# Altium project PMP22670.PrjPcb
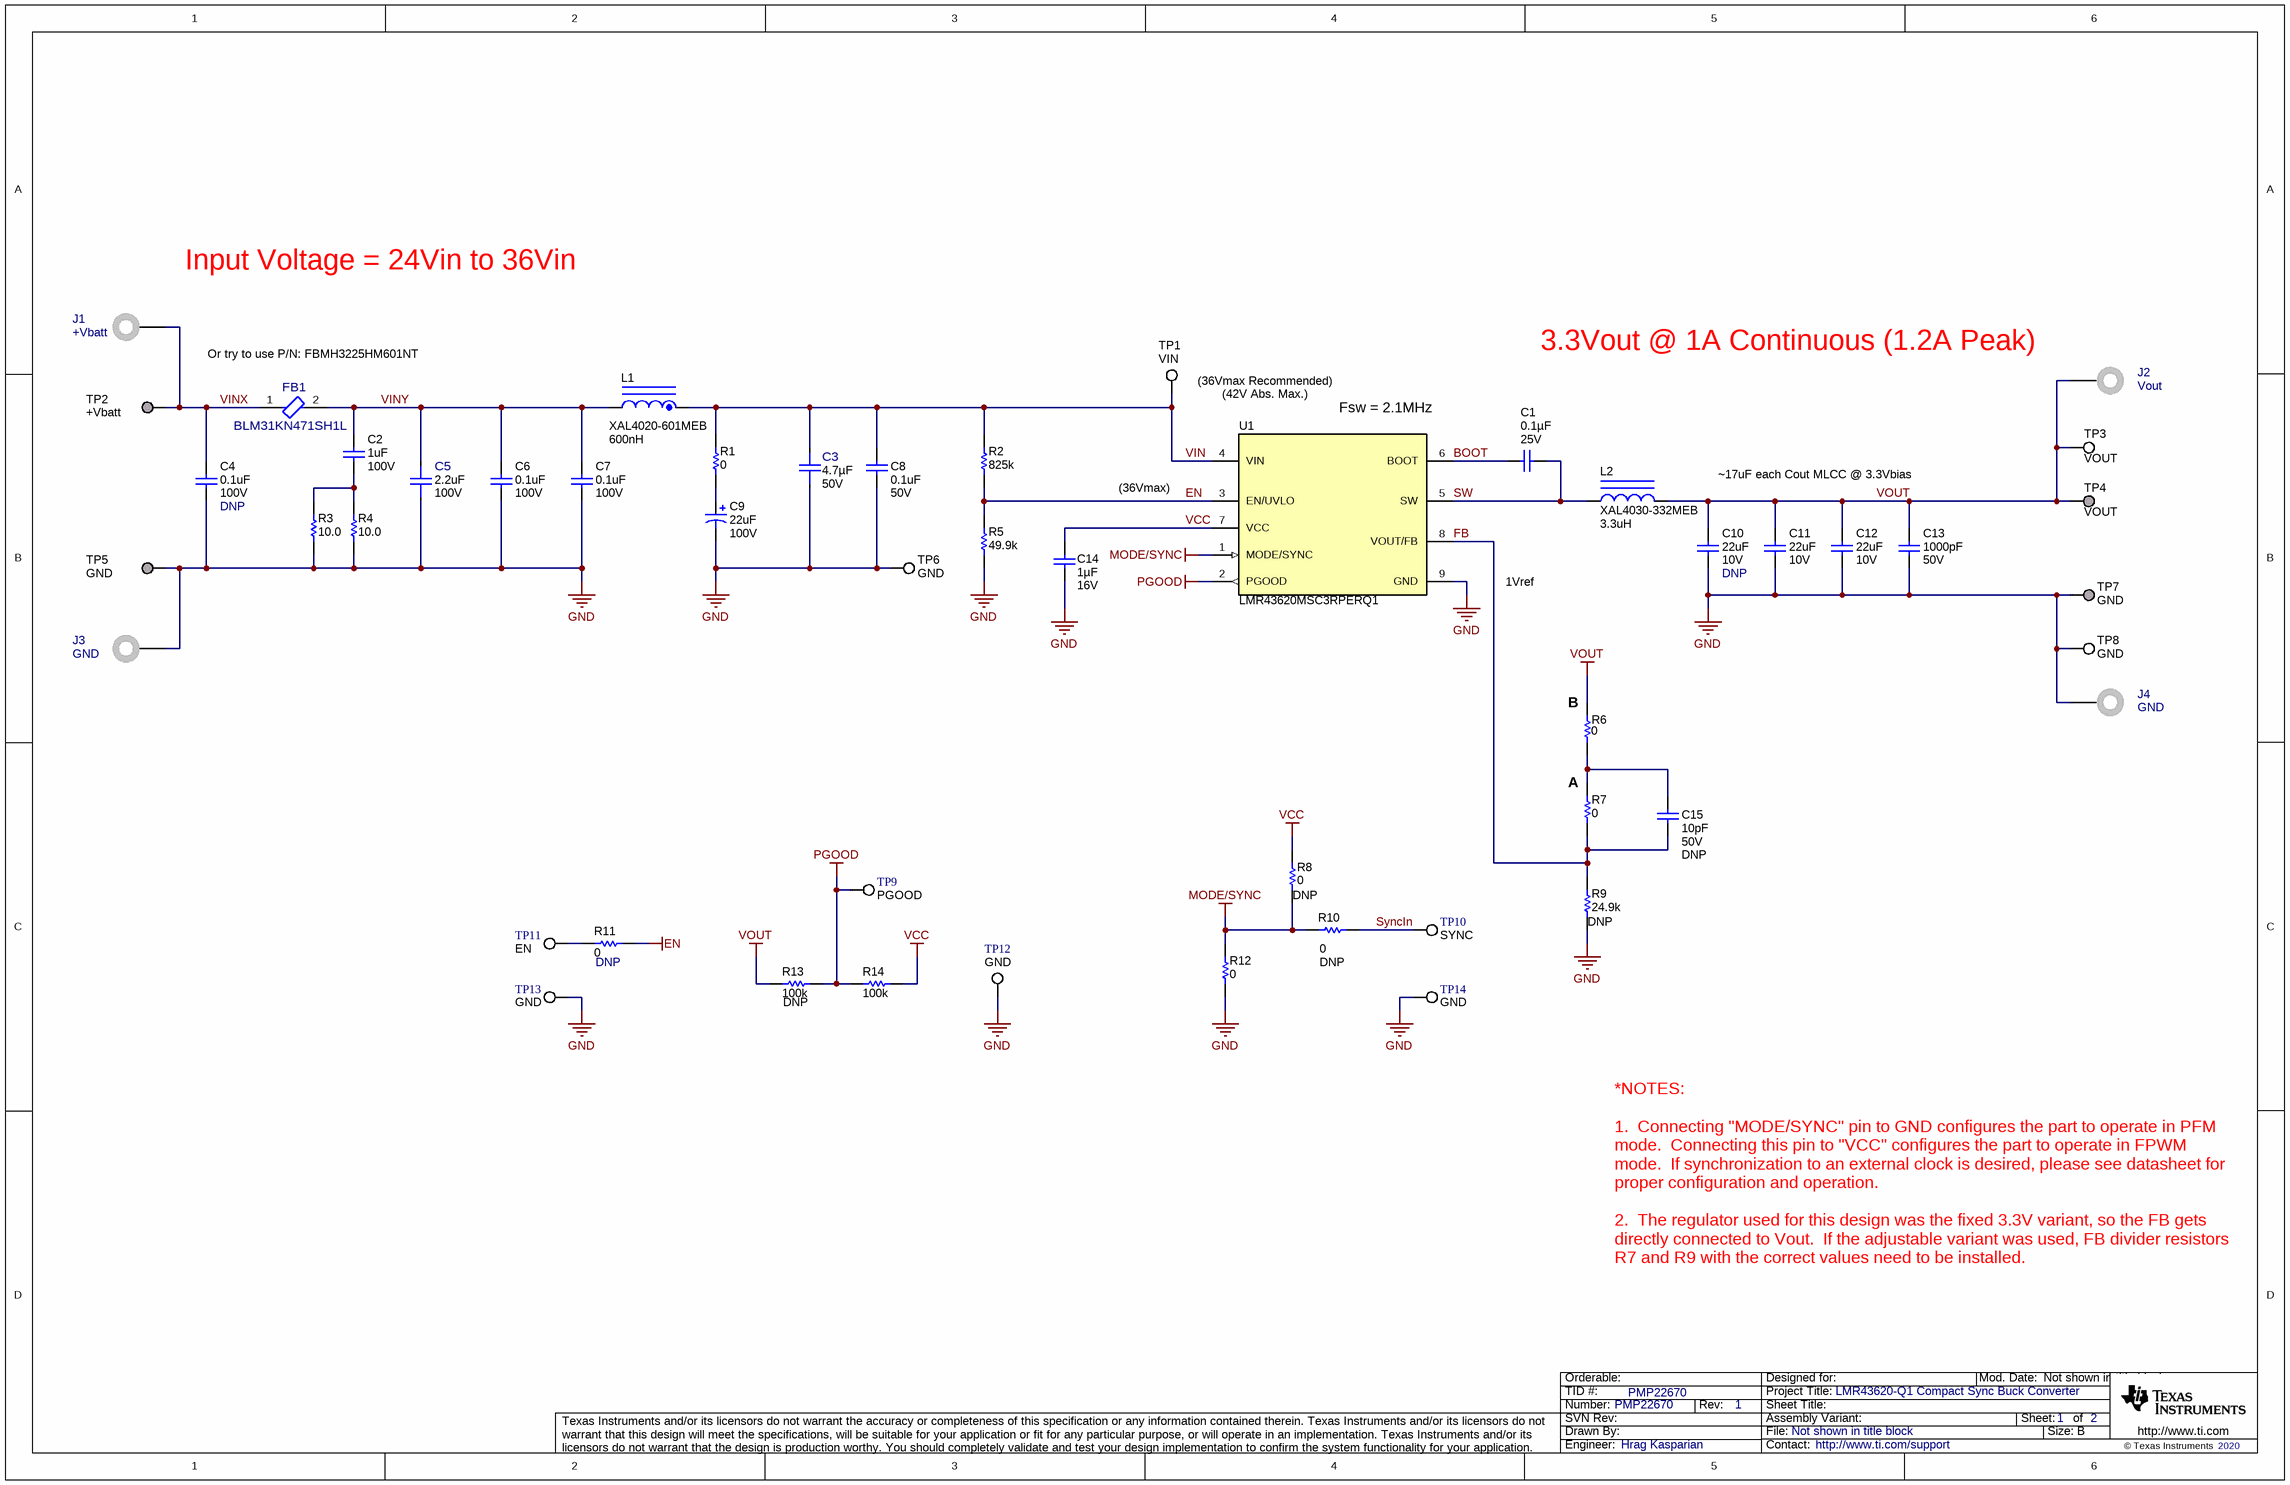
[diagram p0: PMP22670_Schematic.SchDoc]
CopyrightYear: 2020; PCB_Rev: B; PRJ_Engineer: Hrag Kasparian; PRJ_Number: PMP22670; PRJ_Title: LMR43620-Q1 Compact Sync Buck Converter; SCH_Rev: 1; TechSupport: http://www.ti.com/support; TID: PMP22670
2 sheets, 63 parts. Net scope: global (net labels, ports and power ports of the same name join across sheets).
Board file: PMP22670_PCB.PcbDoc
Sheets:
  PMP22670_Schematic.SchDoc
  PMP22670_Hardware.SchDoc

## Sheet PMP22670_Schematic.SchDoc
size 431 x 279 mm; Date: Not shown in title block; ApprovedBy: Not shown in title block; CheckedBy: Not shown in title block; Author: Not shown in title block; CompanyName: Not shown in title block; Engineer: Not shown in title block; Organization: Not shown in title block; Address1: Not shown in title block; Address2: Not shown in title block; Address3: Not shown in title block; Address4: Not shown in title block; DocumentNumber: 1; Revision: Use project parameter SCH_Rev; SheetNumber: 1; SheetTotal: 2; PageSetup: Record=PageOptions¦CenterHorizontal=True¦CenterVertical=True¦PrintScale=1.00¦XCorrection=1.00¦YCorrection=1.00¦PrintKind=0¦BorderSize=5000000¦LeftOffset=0¦BottomOffset=0¦Orientation=2¦PaperLength=1000¦PaperWidth=1000¦Scale=100¦PaperSource=15¦PrintQuality=600¦MediaType=1¦DitherType=10¦PaperKind=Letter¦PrintScaleMode=1

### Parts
C1  VDC_V: 25V  ValueDisplayed: 0.1µF  [0402S]  (hidden comment: CGA2B3X7R1E104K050BB)
C2  VDC_V: 100V  ValueDisplayed: 1uF  [1206_180]  (hidden comment: CGA5L2X7R2A105K160AA)
C3  Cap_F: 4.7µF  VDC_V: 50V  [FP-CGA4J1X7R1H475K125AC_0805-MFG]  (hidden comment: CGA4J1X7R1H475K125AC)
C4  DNP  Value2: 100V  ValueDisplayed: 0.1uF  [0805_HV]
C5  VDC_V: 100V  ValueDisplayed: 2.2uF  [FP-HMF325B7225KMHP_1210-MFG]  (hidden comment: HMF325B7225KMHP)
C6  Value2: 100V  ValueDisplayed: 0.1uF  [0805_HV]
C7  Value2: 100V  ValueDisplayed: 0.1uF  [0805_HV]
C8  VDC_V: 50V  ValueDisplayed: 0.1uF  [0402L]  (hidden comment: CGA2B3X7R1H104K050BB)
C9  Value2: 100V  ValueDisplayed: 22uF  [SM_RADIAL_F]
C10  DNP  Value2: 10V  ValueDisplayed: 22uF  [1206_180]
C11  Value2: 10V  ValueDisplayed: 22uF  [1206_180]
C12  Value2: 10V  ValueDisplayed: 22uF  [1206_180]
C13  VDC_V: 50V  ValueDisplayed: 1000pF  [0402L]  (hidden comment: GCM155R71H102KA37D)
C14  Cap_F: 1µF  VDC_V: 16V  [0603S]  (hidden comment: CGA3E1X7R1C105K080AC)
C15  DNP  VDC_V: 50V  ValueDisplayed: 10pF  [0402L]
FB1  BLM31KN471SH1L  [FP-BLM31KN471SH1L_1206-MFG]
J1  +Vbatt  [Keystone575-8]
J2  Vout  [Keystone575-8]
J3  GND  [Keystone575-8]
J4  GND  [Keystone575-8]
L1  XAL4020-601MEB  ValueDisplayed: 600nH  [XAL4020]
L2  XAL4030-332MEB  ValueDisplayed: 3.3uH  [XAL4030]
R1  ValueDisplayed: 0  [2512]  (hidden comment: CRCW25120000Z0EG)
R2  ValueDisplayed: 825k  [0402S]  (hidden comment: CRCW0402825KFKED)
R3  ValueDisplayed: 10.0  [2010L]  (hidden comment: CRCW201010R0FKEF)
R4  ValueDisplayed: 10.0  [2010L]  (hidden comment: CRCW201010R0FKEF)
R5  ValueDisplayed: 49.9k  [0402L]  (hidden comment: CRCW040249K9FKED)
R6  ValueDisplayed: 0  [0402L]
R7  ValueDisplayed: 0  [0402L]  (hidden comment: CRCW04020000Z0ED)
R8  DNP  ValueDisplayed: 0  [0402L]
R9  DNP  ValueDisplayed: 24.9k  [0402L]
R10  DNP  ValueDisplayed: 0  [0402L]
R11  DNP  ValueDisplayed: 0  [0402L]
R12  ValueDisplayed: 0  [0402L]
R13  DNP  ValueDisplayed: 100k  [0402L]
R14  ValueDisplayed: 100k  [0402L]  (hidden comment: CRCW0402100KJNED)
TP1  VIN  [Testpoint_Keystone_Miniature]
TP2  +Vbatt  [Keystone1502-2]
TP3  VOUT  [Testpoint_Keystone_Miniature]
TP4  VOUT  [Keystone1502-2]
TP5  GND  [Keystone1502-2]
TP6  GND  [Testpoint_Keystone_Miniature]
TP7  GND  [Keystone1502-2]
TP8  GND  [Testpoint_Keystone_Miniature]
TP9  PGOOD  [Testpoint_Keystone_Miniature]
TP10  SYNC  [Testpoint_Keystone_Miniature]
TP11  EN  [Testpoint_Keystone_Miniature]
TP12  GND  [Testpoint_Keystone_Miniature]
TP13  GND  [Testpoint_Keystone_Miniature]
TP14  GND  [Testpoint_Keystone_Miniature]
U1  LMR43620MSC3RPERQ1  [RPE0009A]

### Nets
EN: R2.1 R5.2 R11.2 U1.3(EN/UVLO)
GND: C3.1 C4.2 C5.1 C6.2 C7.2 C8.2 C9.2(-) C10.1 C11.1 C12.1 C13.1 C14.2 J3.1 J4.1 R3.1 R4.1 R5.1 R9.2 R12.2 TP5.1 TP6.1 TP7.1 TP8.1 TP12.1 TP13.1 TP14.1 U1.9(GND)
MODE/SYNC: R8.2 R10.2 R12.1 U1.1(MODE/SYNC)
PGOOD: R13.1 R14.2 TP9.1 U1.2(PGOOD)
VCC: C14.1 R8.1 R14.1 U1.7(VCC)
VOUT: C10.2 C11.2 C12.2 C13.2 J2.1 L2.1 R6.2 R13.2 TP3.1 TP4.1
BOOT: C1.1 U1.6(BOOT)
FB: C15.2 R7.1 R9.1 U1.8(VOUT/FB)
SW: C1.2 L2.2 U1.5(SW)
SyncIn: R10.1 TP10.1
VIN: C3.2 C8.1 L1.1 R1.2 R2.2 TP1.1 U1.4(VIN)
VINX: C4.1 FB1.1 J1.1 TP2.1
VINY: C2.1 C5.2 C6.1 C7.1 FB1.2 L1.2
NetC2_2: C2.2 R3.2 R4.2
NetC9_1: C9.1(+) R1.1
NetC15_1: C15.1 R6.1 R7.2
NetR11_1: R11.1 TP11.1

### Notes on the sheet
- Input Voltage = 24Vin to 36Vin
- (near FB1) Or try to use P/N: FBMH3225HM601NT
- 3.3Vout @ 1A Continuous (1.2A Peak)
- (near TP1) (36Vmax Recommended)
- (42V Abs. Max.)
- (near U1) Fsw = 2.1MHz
- (36Vmax)
- 7uF each Cout MLCC @ 3.3Vbias
- 1Vref
- (near R6) B
- (near R7) A
- *NOTES:
  1.  Connecting "MODE/SYNC" pin to GND configures the part to operate in PFM mode.  Connecting this pin to "VCC" configures the part to operate in FPWM mode.  If synchronization to an external clock is desired, please see datasheet for proper configuration and operation.
  2.  The regulator used for this design was the fixed 3.3V variant, so the FB gets directly connected to Vout.  If the adjustable variant was used, FB divider resistors R7 and R9 with the correct values need to be installed.

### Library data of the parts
C1 = CMP-0080610-1: CAP, CERM, 0.1 µF, 25 V,+/- 10%, X7R, AEC-Q200 Grade 1, 0402; Manufacturer: TDK; TaMin_C: -55°C; Polarized: N; SizeAreaWB_mm2: 3; U/M: EA; Value: 0.1uF; TaMax_C: 125°C; SizeZ_mm: 0.6; SizeX_mm: 1; SizeY_mm: 0.5; Cap_Case: 0402; AEC Qualified: Y; Cap_F: 100nF; AEC Category: Q200
C2 = CMP-0008779-2: CAP, CERM, 1 uF, 100 V, +/- 10%, X7R, AEC-Q200 Grade 1, 1206; Manufacturer: TDK; TaMin_C: -55°C; ESR_ohm: 4.575m; Polarized: N; SizeAreaWB_mm2: 10.92; Value1: 0.004575 ohm; U/M: EA; Value: 1uF; TaMax_C: 125°C; SizeZ_mm: 1.8; SizeX_mm: 3.2; SizeY_mm: 1.6; SizeArea_mm2: 5.12; AEC Qualified: Y; Cap_F: 1µF; IRMS_A: 3.39639A; AEC Grade: 1; AEC Category: Q200
C3 = CMP-0090082-1: Cap Ceramic 4.7uF 50V X7R 10% Pad SMD 0805 +125°C Automotive T/R; Manufacturer: TDK Corporation; TempCo: 15%; Value: 4.7µF; Tolerance_%: 0.1%; SizeZ_mm: 1.45mm; AEC Qualified: Yes; AEC Grade: Grade 1
C4 C6 C7 = CMP-0007969-2: CAP, CERM, 0.1 uF, 100 V, +/- 10%, X7R, AEC-Q200 Grade 1, 0805; Manufacturer: TDK; PartNumber: CGA4J2X7R2A104K125AA; TaMin_C: -55°C; ESR_ohm: 0.020726; Polarized: N; SizeAreaWB_mm2: 6.75; Value1: 0.020726 ohm; U/M: EA; Value: 0.1uF; TaMax_C: 125°C; SizeZ_mm: 1.45; SizeX_mm: 2; SizeY_mm: 1.25; Cap_Case: 0805; SizeArea_mm2: 2.5; CompType: Capacitor; AEC Qualified: Y; Cap_F: 100nF; IRMS_A: 1.456A; AEC Grade: 1; AEC Category: Q200
C5 = CMP-0089259-1: 2.2µF ±10% 100V Ceramic Capacitor X7R 1210 (3225 Metric); Manufacturer: Taiyo Yuden; TempCo: 15%; SizeZ_mm: 2.7mm; AEC Qualified: Yes; AEC Grade: Grade 1
C8 = CMP-0006325-2: CAP, CERM, 0.1 uF, 50 V, +/- 10%, X7R, AEC-Q200 Grade 1, 0402; Manufacturer: TDK; TaMin_C: -55°C; Polarized: N; SizeAreaWB_mm2: 3; Value1: 0.039064 ohm; U/M: EA; Value: 0.1uF; TaMax_C: 125°C; SizeZ_mm: 0.6; SizeX_mm: 1; SizeY_mm: 0.5; Cap_Case: 0402; AEC Qualified: Y; Cap_F: 100nF; AEC Category: Q200; ESR_ohm: 0.039064; IRMS_A: 814.669mA
C9 = CMP-0011202-2: CAP, AL, 22 uF, 100 V, +/- 20%, 1.3 ohm, AEC-Q200 Grade 2, SMD; Manufacturer: Panasonic; PartNumber: EEE-FK2A220P; TaMin_C: -55°C; ESR_ohm: 1.3; Polarized: Y; SizeAreaWB_mm2: 123.6; Value1: 1.3 ohm; U/M: EA; Value: 22uF; TaMax_C: 105°C; SizeZ_mm: 10.2; SizeX_mm: 10; SizeY_mm: 8.3; Cap_Case: F; SizeArea_mm2: 83; CompType: Capacitor; Cap_F: 22µF; IRMS_A: 1.3dA; AEC Grade: 2; AEC Category: Q200
C10-C12 = CMP-0008811-2: CAP, CERM, 22 uF, 10 V, +/- 10%, X7R, AEC-Q200 Grade 1, 1206; Manufacturer: MuRata; PartNumber: GCM31CR71A226KE02; TaMin_C: -55°C; Polarized: N; SizeAreaWB_mm2: 10.92; Value1: Unknown; U/M: EA; Value: 22uF; TaMax_C: 125°C; SizeZ_mm: 1.8; SizeX_mm: 3.2; SizeY_mm: 1.6; Cap_Case: 1206; SizeArea_mm2: 5.12; CompType: Capacitor; AEC Qualified: Y; Cap_F: 22µF; AEC Grade: 1; AEC Category: Q200
C13 = CMP-0006354-2: CAP, CERM, 1000 pF, 50 V, +/- 10%, X7R, AEC-Q200 Grade 1, 0402; Manufacturer: MuRata; TaMin_C: -55°C; Polarized: N; SizeAreaWB_mm2: 3; Value1: Unknown; U/M: EA; Value: 1000pF; TaMax_C: 125°C; SizeZ_mm: 0.6; SizeX_mm: 1; SizeY_mm: 0.5; Cap_Case: 0402; AEC Qualified: Y; Cap_F: 1nF; AEC Category: Q200
C14 = CMP-0079607-1: CAP, CERM, 1 µF, 16 V,+/- 10%, X7R, AEC-Q200 Grade 1, 0603; Manufacturer: TDK; TaMin_C: -55°C; Polarized: N; SizeAreaWB_mm2: 4.68; U/M: EA; Value: 1uF; TaMax_C: 125°C; SizeZ_mm: 1; SizeX_mm: 1.6; SizeY_mm: 0.8; Cap_Case: 0603; SizeArea_mm2: 1.28; AEC Qualified: Y; AEC Category: Q200
C15 = CMP-0860290-1: CAP, CERM, 10 pF, 50 V,+/- 5%, C0G/NP0, AEC-Q200 Grade 1, 0402; Manufacturer: MuRata; PartNumber: GCM1555C1H100JA16D; TaMin_C: -55°C; Polarized: N; SizeAreaWB_mm2: 3; U/M: EA; Value: 10pF; TaMax_C: 125°C; SizeZ_mm: 0.6; SizeX_mm: 1; SizeY_mm: 0.5; Cap_Case: 0402; AEC Qualified: Y; AEC Category: Q200
FB1 = CMP-0090407-1: 470 Ohms @ 100MHz 1 Power Line Ferrite Bead 1206 (3216 Metric) 4A 20mOhm; Manufacturer: Murata; AEC Grade: Grade 1; SizeZ_mm: 1.8mm; DCR_ohm: 0.02; Tolerance_%: 25%; Impedance At Frequency: 470Ω @ 100MHz; AEC Qualified: Yes
J1-J4 = CMP-0055166-2: Standard Banana Jack, Uninsulated, 8.9mm; Manufacturer: Keystone; PartNumber: 575-8; CT: TRUE; Green_REACh: Passed; CNHeader: FALSE; Green_Lifecycle: Active
L1 = CMP-0060988-2: Inductor, Shielded, Composite, 600 nH, 10.38 A, 0.01 ohm, AEC-Q200 Grade 1, SMD; Manufacturer: Coilcraft; SizeX_mm: 4.3; Green_REACh: Incomplete; Value2: 10.38A; Irms: 11.7A @ 40C rise; SizeArea_mm2: 18.49; Green_Lifecycle: Not Set; AEC Grade: 1; AEC Qualified: Y; DCR_ohm: 0.01; Value: 600nH; Isat: 10.38A @ 30% inductance drop; SizeZ_mm: 2.1; SizeAreaWB_mm2: 28.09; AEC Category: Q200
L2 = CMP-0060989-1: Inductor, Shielded, Composite, 3.3 uH, 5.5 A, 0.026 ohm, SMD; Manufacturer: Coilcraft; Irms: 6.6A @ 40C rise; SizeZ_mm: 3.1; DCR_ohm: 0.026; Ind_H: 3.3µH; Isat: 5.5A @ 30% inductance drop; Green_Lifecycle: Not Set; SizeAreaWB_mm2: 25; Green_REACh: Incomplete; Value: 3.3uH; Imax_A: 5.5A; SizeX_mm: 4; SizeArea_mm2: 16; AEC Category: Q200
R1 = CMP-0015864-3: RES, 0, 5%, 1 W, AEC-Q200 Grade 0, 2512; Manufacturer: Vishay-Dale; Power_W: 1W; TempCo: ppm/C; Value_Code: 0000; Value: 0; EIA_Code: E24; SizeX_mm: 6.3; SizeY_mm: 3.2; SizeZ_mm: 0.71; SizeArea_mm2: 20.16; AEC Qualified: Y; AEC Category: Q200
R2 = CMP-0026572-2: RES, 825 k, 1%, 0.063 W, AEC-Q200 Grade 0, 0402; Manufacturer: Vishay-Dale; Power_W: 63mW; TempCo: 100 ppm/C; Value: 825k; EIA_Code: E96; SizeX_mm: 1; SizeY_mm: 0.5; SizeZ_mm: 0.6; Value2: 0.063W; AEC Qualified: Y; VDC_V: 50V; AEC Category: Q200; AEC Grade: 0
R3 = CMP-0016215-3: RES, 10.0, 1%, 0.75 W, AEC-Q200 Grade 0, 2010; Manufacturer: Vishay-Dale; Power_W: 750mW; TempCo: 100 ppm/C; Value_Code: 10R0; Value: 10.0; EIA_Code: E96; Res_ohm: 10; SizeX_mm: 5; SizeY_mm: 2.5; SizeZ_mm: 1.66; Value2: 0.75W; SizeArea_mm2: 12.5; AEC Qualified: Y; VDC_V: 400V; AEC Grade: 0; AEC Category: Q200
R4 = CMP-0016215-3: RES, 10.0, 1%, 0.75 W, AEC-Q200 Grade 0, 2010; Manufacturer: Vishay-Dale; Power_W: 750mW; TempCo: 100 ppm/C; Value_Code: 10R0; Value: 10.0; EIA_Code: E96; Res_ohm: 10; SizeX_mm: 5; SizeY_mm: 2.5; SizeZ_mm: 1.66; Value2: 0.75W; SizeArea_mm2: 12.5; AEC Qualified: Y; VDC_V: 400V; AEC Category: Q200; AEC Grade: 0
R5 = CMP-0026403-2: RES, 49.9 k, 1%, 0.063 W, AEC-Q200 Grade 0, 0402; Manufacturer: Vishay-Dale; Power_W: 63mW; TempCo: 100 ppm/C; Value: 49.9k; SizeZ_mm: 0.6; AEC Qualified: Y; VDC_V: 50V; AEC Grade: 0; Value_Code: 49k9; EIA_Code: E96; SizeX_mm: 1; SizeY_mm: 0.5; Value2: 0.063W; AEC Category: Q200
R6 R8 R10 R12 = CMP-0026822-3: RES, 0, 5%, 0.063 W, AEC-Q200 Grade 0, 0402; Manufacturer: Vishay-Dale; PartNumber: CRCW04020000Z0ED; Power_W: 63mW; TempCo: 200 ppm/C; Value_Code: 0000; Value: 0; EIA_Code: E24; SizeX_mm: 1; SizeY_mm: 0.5; SizeZ_mm: 0.6; Value2: 0.063W; AEC Qualified: Y; VDC_V: 50V; AEC Category: Q200
R7 = CMP-0026822-3: RES, 0, 5%, 0.063 W, AEC-Q200 Grade 0, 0402; Manufacturer: Vishay-Dale; Power_W: 63mW; TempCo: 200 ppm/C; Value_Code: 0000; Value: 0; EIA_Code: E24; SizeX_mm: 1; SizeY_mm: 0.5; SizeZ_mm: 0.6; Value2: 0.063W; AEC Qualified: Y; VDC_V: 50V; AEC Category: Q200
R9 = CMP-0026196-2: RES, 24.9 k, 1%, 0.063 W, AEC-Q200 Grade 0, 0402; Manufacturer: Vishay-Dale; PartNumber: CRCW040224K9FKED; Power_W: 63mW; TempCo: 100 ppm/C; Value_Code: 24k9; Value: 24.9k; EIA_Code: E96; SizeX_mm: 1; SizeY_mm: 0.5; SizeZ_mm: 0.6; Value2: 0.063W; AEC Qualified: Y; VDC_V: 50V; AEC Category: Q200; AEC Grade: 0
R11 = CMP-0026822-3: RES, 0, 5%, 0.063 W, AEC-Q200 Grade 0, 0402; Manufacturer: Vishay-Dale; PartNumber: CRCW04020000Z0ED; Power_W: 63mW; TempCo: 200 ppm/C; Value_Code: 0000; Value: 0; EIA_Code: E24; SizeX_mm: 1; SizeY_mm: 0.5; SizeZ_mm: 0.6; Value2: 0.063W; CompType: Resistor; AEC Qualified: Y; VDC_V: 50V; AEC Category: Q200
R13 = CMP-0026823-3: RES, 100 k, 5%, 0.063 W, AEC-Q200 Grade 0, 0402; Manufacturer: Vishay-Dale; PartNumber: CRCW0402100KJNED; Power_W: 63mW; TempCo: 200 ppm/C; Value: 100k; EIA_Code: E24; SizeX_mm: 1; SizeY_mm: 0.5; SizeZ_mm: 0.6; Value2: 0.063W; AEC Qualified: Y; VDC_V: 50V; AEC Category: Q200; AEC Grade: 0
R14 = CMP-0026823-3: RES, 100 k, 5%, 0.063 W, AEC-Q200 Grade 0, 0402; Manufacturer: Vishay-Dale; Power_W: 63mW; TempCo: 200 ppm/C; Value: 100k; EIA_Code: E24; SizeX_mm: 1; SizeY_mm: 0.5; SizeZ_mm: 0.6; Value2: 0.063W; AEC Qualified: Y; VDC_V: 50V; AEC Category: Q200; AEC Grade: 0
TP1 TP3 TP6 TP8 = CMP-0055152-1: Test Point, Miniature, SMT; Manufacturer: Keystone; PartNumber: 5015; CNHeader: FALSE; Green_Lifecycle: Active; Green_REACh: Passed; CT: TRUE
TP2 TP4 TP5 TP7 = CMP-0055113-1: Terminal, Turret, TH, Double; Manufacturer: Keystone; PartNumber: 1502-2; CT: FALSE; Green_REACh: Passed; CompType: Turret Terminal; Green_Lifecycle: Active
TP9-TP11 TP13 TP14 = CMP-0055152-1: Test Point, Miniature, SMT; Manufacturer: Keystone; CNHeader: FALSE; Green_Lifecycle: Active; Green_REACh: Passed; CT: TRUE
TP12 = CMP-0055152-1: Test Point, Miniature, SMT; Manufacturer: Keystone; CT: TRUE; Green_REACh: Passed; CNHeader: FALSE; Green_Lifecycle: Active
U1 = CMP-0860883-2: Industry's lowest Iq 36V 2.0A/1.0A –DC Synchronous Buck Regulator, RPE0009A (VQFN-9); Manufacturer: Texas Instruments; SizeY_mm: 2; SizeZ_mm: 1; SizeAreaWB_mm2: 9; AEC Category: Q200; CompType: IC; AEC Qualified: Y; SizeArea_mm2: 4

## Sheet PMP22670_Hardware.SchDoc
size 431 x 279 mm; Date: Not shown in title block; ApprovedBy: Not shown in title block; CheckedBy: Not shown in title block; Author: Not shown in title block; CompanyName: Not shown in title block; Engineer: Not shown in title block; Organization: Not shown in title block; Address1: Not shown in title block; Address2: Not shown in title block; Address3: Not shown in title block; Address4: Not shown in title block; DocumentNumber: 2; Revision: Use project parameter SCH_Rev; SheetNumber: 2; SheetTotal: 2; PageSetup: Record=PageOptions¦CenterHorizontal=True¦CenterVertical=True¦PrintScale=1.00¦XCorrection=1.00¦YCorrection=1.00¦PrintKind=0¦BorderSize=5000000¦LeftOffset=0¦BottomOffset=0¦Orientation=2¦PaperLength=1000¦PaperWidth=1000¦Scale=100¦PaperSource=15¦PrintQuality=600¦MediaType=1¦DitherType=10¦PaperKind=Letter¦PrintScaleMode=1
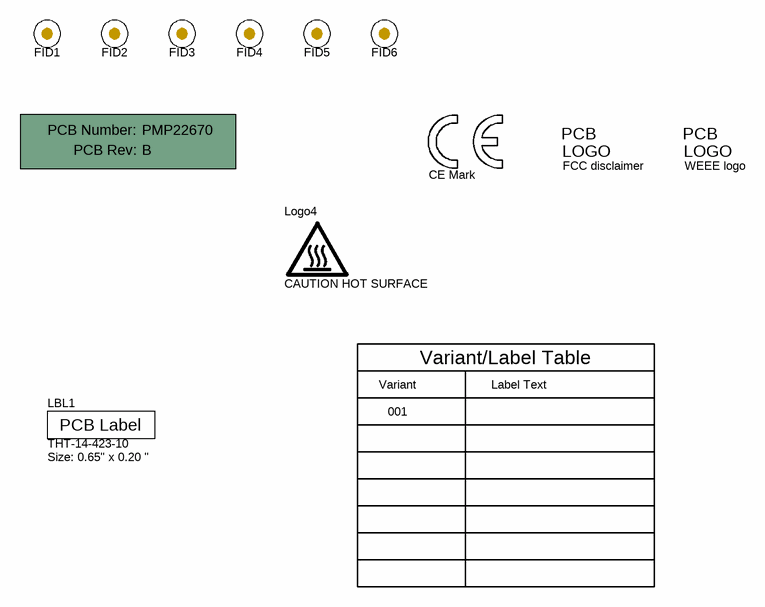
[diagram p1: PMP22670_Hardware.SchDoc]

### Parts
!PCB1  Printed Circuit Board  (value not drawn)  (mechanical)
FID1  Fiducial  [Fiducial10-20]  (value not drawn)
FID2  Fiducial  [Fiducial10-20]  (value not drawn)
FID3  Fiducial  [Fiducial10-20]  (value not drawn)
FID4  Fiducial  [Fiducial10-20]  (value not drawn)
FID5  Fiducial  [Fiducial10-20]  (value not drawn)
FID6  Fiducial  [Fiducial10-20]  (value not drawn)
LBL1  THT-14-423-10  Note: Size: 0.65" x 0.20 "  [Label_650x200]
Logo1  CE Mark  [CE_Mark_5mm]  (no BOM)
Logo2  FCC disclaimer  [FCC_disclaimer]  (no BOM)
Logo3  WEEE logo  [WEEE_Minimum]  (no BOM)
Logo4  CAUTION HOT SURFACE  [IEC_HotSurface_Small]  (no BOM)

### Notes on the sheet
- Variant
- Variant/Label Table
- Label Text
- 001

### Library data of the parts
!PCB1 = CMP-0003618-2: Manufacturer: Any; PartNumber: PMP22670
FID1-FID6 = CMP-0077181-1: Fiducial mark.  There is nothing to buy or mount.
LBL1 = CMP-0003625-1: Thermal Transfer Printable Labels, 0.650" W x 0.200" H - 10,000 per roll; Manufacturer: Brady; CompType: Label
Logo1 = CMP-0074844-1: SymbolCreator: a0412235
Logo2 = CMP-0074847-1: FCC_disclaimer; Library Reference: Logo
Logo3 = CMP-0074769-1
Logo4 = CMP-0074837-1: IEC 61010-1 Hot Surface Warning; Library Reference: IEC_HotSurface; SymbolCreator: a0412235

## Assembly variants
001: not fitted C4 C10 C15 FID1 FID2 FID3 FID4 FID5 FID6 R8 R9 R10 R11 R13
